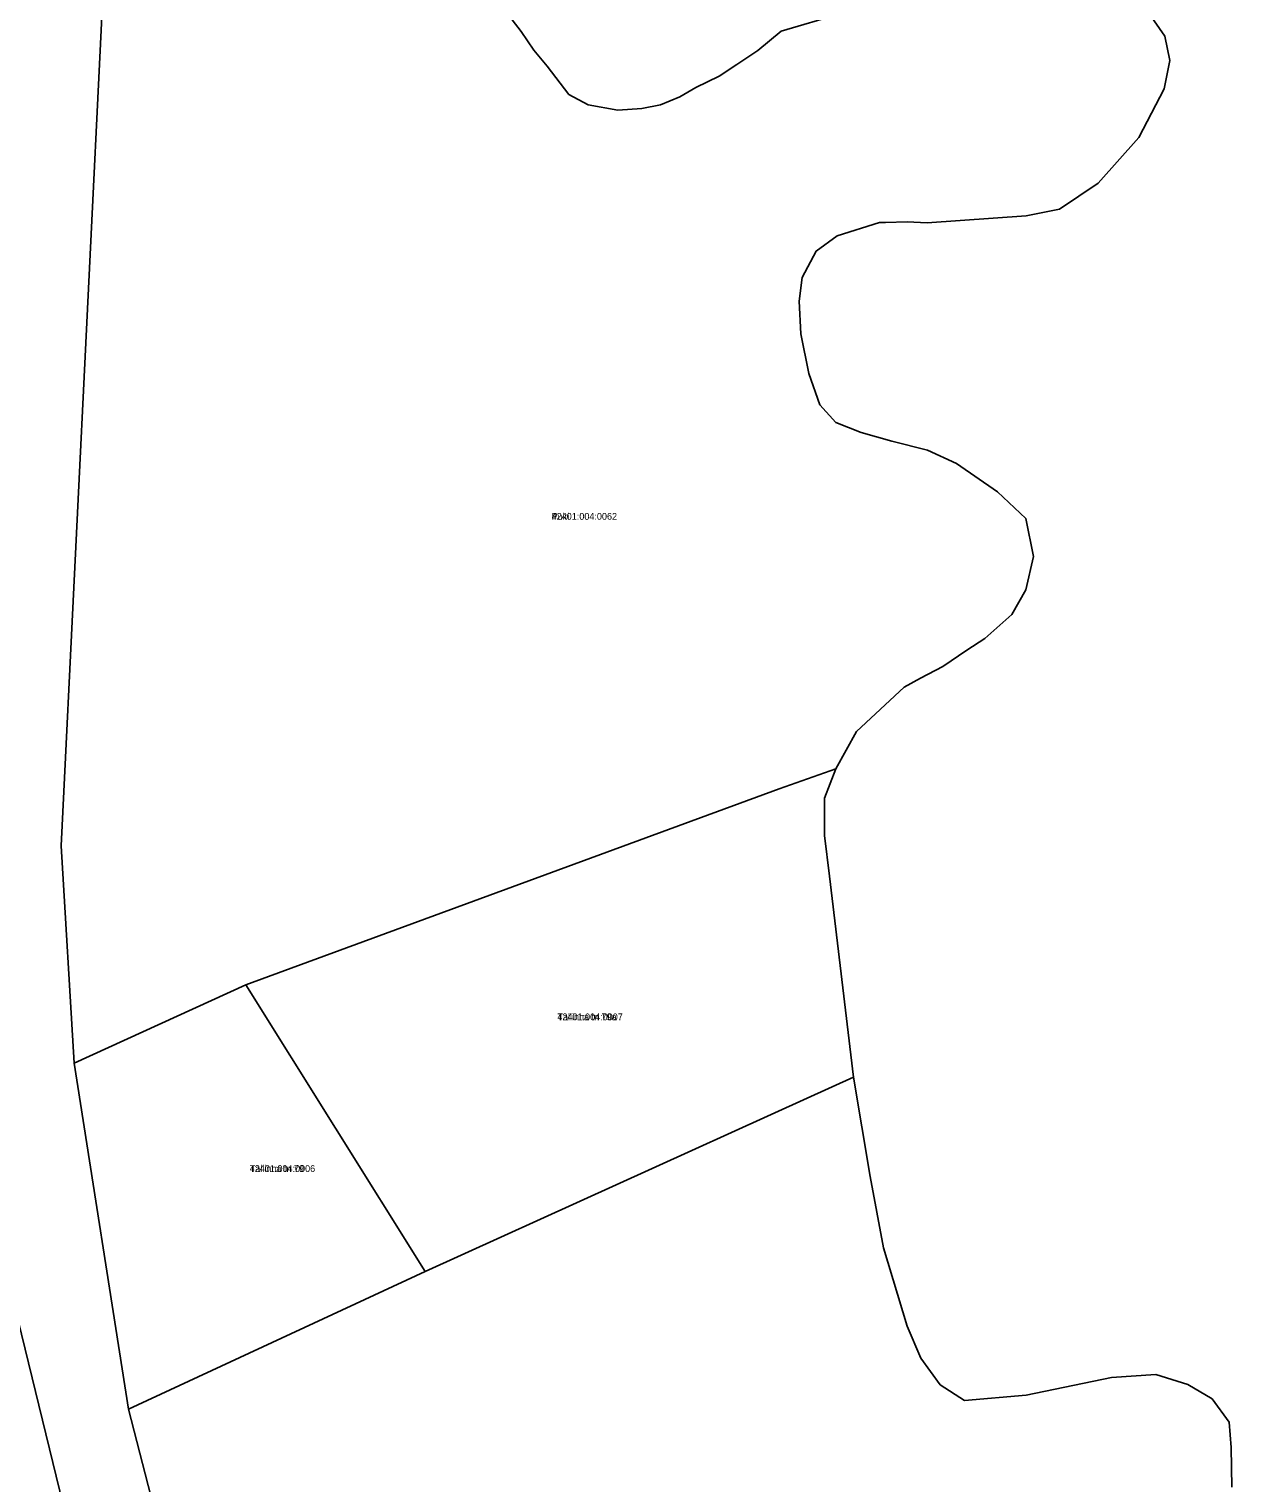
# Model space of a CAD drawing. Extents: x 595979 to 597983, y 6604231 to 6607350.
# Drawn here: x 597468 to 597734.7, y 6604839.1 to 6605161.4 of the extents above; entities that cross this region are included whole.
import ezdxf

# ---------------------------------------------------------------- set-up
doc = ezdxf.new("R2010")
doc.units = 0
for name, color, linetype in [('L_AADRESS', 7, 'Continuous'), ('PIIR', 7, 'Continuous'), ('TUNNUS', 7, 'Continuous')]:
    doc.layers.add(name, color=color, linetype=linetype)

msp = doc.modelspace()

# ---------------------------------------------------------------- linework, layer by layer
at = {"layer": 'PIIR'}
for points in [[(597491.74, 6604767.94), (597460.13, 6604897.15), (597453.23, 6604975.44), (597460.84, 6605133.45), (597461.82, 6605155.54), (597462.44, 6605169.92), (597464.18, 6605199.35), (597465.36, 6605215.89), (597466.32, 6605232.67), (597467.99, 6605256.4), (597471.01, 6605303.31), (597471.58, 6605313.69), (597473.22, 6605343.42), (597478.52, 6605366.25), (597479.63, 6605378.15), (597480.24, 6605385.69), (597483.61, 6605418.8), (597487.25, 6605511.01)], [(597498.55, 6605497.68), (597495.69, 6605445.75), (597493.85, 6605419.46), (597492.15, 6605393.93), (597494.55, 6605393.47), (597494.02, 6605384.17), (597495.31, 6605356.06), (597492.19, 6605325.76), (597489.28, 6605315.53), (597487.66, 6605285.55), (597485.7, 6605255.55), (597484.3, 6605225.65), (597482.84, 6605196.09), (597481.62, 6605165.89), (597484.23, 6605165.63), (597475.17, 6604980.33), (597478.02, 6604932.13), (597490.06, 6604855.41), (597496.29, 6604831.36)], [(597572.35, 6605166.96), (597577.13, 6605160.86), (597579.91, 6605156.73), (597582.88, 6605153.16), (597587.71, 6605146.85), (597592, 6605144.62), (597598.52, 6605143.42), (597603.85, 6605143.76), (597607.97, 6605144.62), (597612.26, 6605146.34), (597615.86, 6605148.4), (597621.01, 6605150.97), (597624.96, 6605153.55), (597629.6, 6605156.64), (597634.79, 6605160.93), (597647.84, 6605164.75)], [(597715.72, 6605165.62), (597719.78, 6605159.82), (597720.9, 6605154.4), (597719.66, 6605148.14), (597714.03, 6605137.34), (597705.03, 6605127.25), (597696.43, 6605121.49), (597689.05, 6605120.01), (597667.12, 6605118.46), (597662.67, 6605118.62), (597657.85, 6605118.49), (597656.57, 6605118.5), (597647.18, 6605115.55), (597642.5, 6605112.17), (597639.44, 6605106.28), (597638.78, 6605101.06), (597639.15, 6605093.85), (597640.89, 6605085.05), (597643.35, 6605078.09), (597646.88, 6605074.13), (597652.49, 6605071.97), (597659.28, 6605070.01), (597667.16, 6605068.01), (597673.62, 6605065.07), (597682.74, 6605058.82), (597688.98, 6605052.86), (597690.7, 6605044.45), (597688.98, 6605037.07), (597685.89, 6605031.58), (597679.88, 6605026.26), (597675.93, 6605023.69), (597670.61, 6605020.08), (597665.63, 6605017.51), (597662.03, 6605015.45), (597651.46, 6605005.64), (597646.85, 6604997.35), (597634.32, 6604992.96), (597516.11, 6604949.47), (597478.02, 6604932.13), (597475.17, 6604980.33), (597484.23, 6605165.63)], [(597496.29, 6604831.36), (597490.06, 6604855.41), (597555.86, 6604885.93), (597640.54, 6604924.35), (597650.78, 6604929), (597654.5, 6604907), (597657.43, 6604891.21), (597662.66, 6604873.79), (597665.74, 6604866.76), (597670, 6604860.84), (597675.42, 6604857.31), (597689.07, 6604858.54), (597707.99, 6604862.45), (597717.8, 6604863.11), (597724.9, 6604860.87), (597730.28, 6604857.7), (597734.1, 6604852.56), (597734.52, 6604846.89), (597734.68, 6604838.12)]]:
    msp.add_lwpolyline(points, dxfattribs=at)
for points in [[(597516.11, 6604949.47), (597634.32, 6604992.96), (597646.85, 6604997.35), (597644.39, 6604990.88), (597644.38, 6604982.62), (597645.45, 6604973.55), (597650.78, 6604929), (597640.54, 6604924.35), (597555.86, 6604885.93)], [(597478.02, 6604932.13), (597516.11, 6604949.47), (597555.86, 6604885.93), (597490.06, 6604855.41)], [(597036.92, 6604395.59), (596986.98, 6604522.29), (596975.34, 6604552.03), (597190.21, 6604702.64), (597431.6, 6604855.49), (597424.92, 6604868.01), (597460.13, 6604897.15), (597491.74, 6604767.94), (597361.63, 6604743.85), (597410.5, 6604564.41), (597223.16, 6604412.75), (597062.73, 6604330.32)]]:
    msp.add_lwpolyline(points, close=True, dxfattribs=at)

# ---------------------------------------------------------------- texts
at = {"layer": 'L_AADRESS'}
for s, p in [('Puki', (597583.87, 6605052.6)), ('Tallinna tn 79a', (597585.14, 6604941.64)), ('Tallinna tn 79', (597516.94, 6604908.01))]:
    msp.add_text(s, height=1.5, dxfattribs=at).set_placement(p)
at = {"layer": 'TUNNUS'}
for s, p in [('42401:004:0062', (597583.87, 6605052.6)), ('42401:004:0007', (597585.14, 6604941.64)), ('42401:004:0006', (597516.94, 6604908.01))]:
    msp.add_text(s, height=1.5, dxfattribs=at).set_placement(p)

doc.saveas('drawing.dxf')
